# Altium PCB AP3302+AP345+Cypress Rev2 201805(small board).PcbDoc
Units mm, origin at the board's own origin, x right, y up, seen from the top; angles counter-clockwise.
Board outline 316.8 x 235.8 mm, 2 copper layers (Top Layer, Bottom Layer); 44 components, 66 nets, 160 pads, 51 vias.
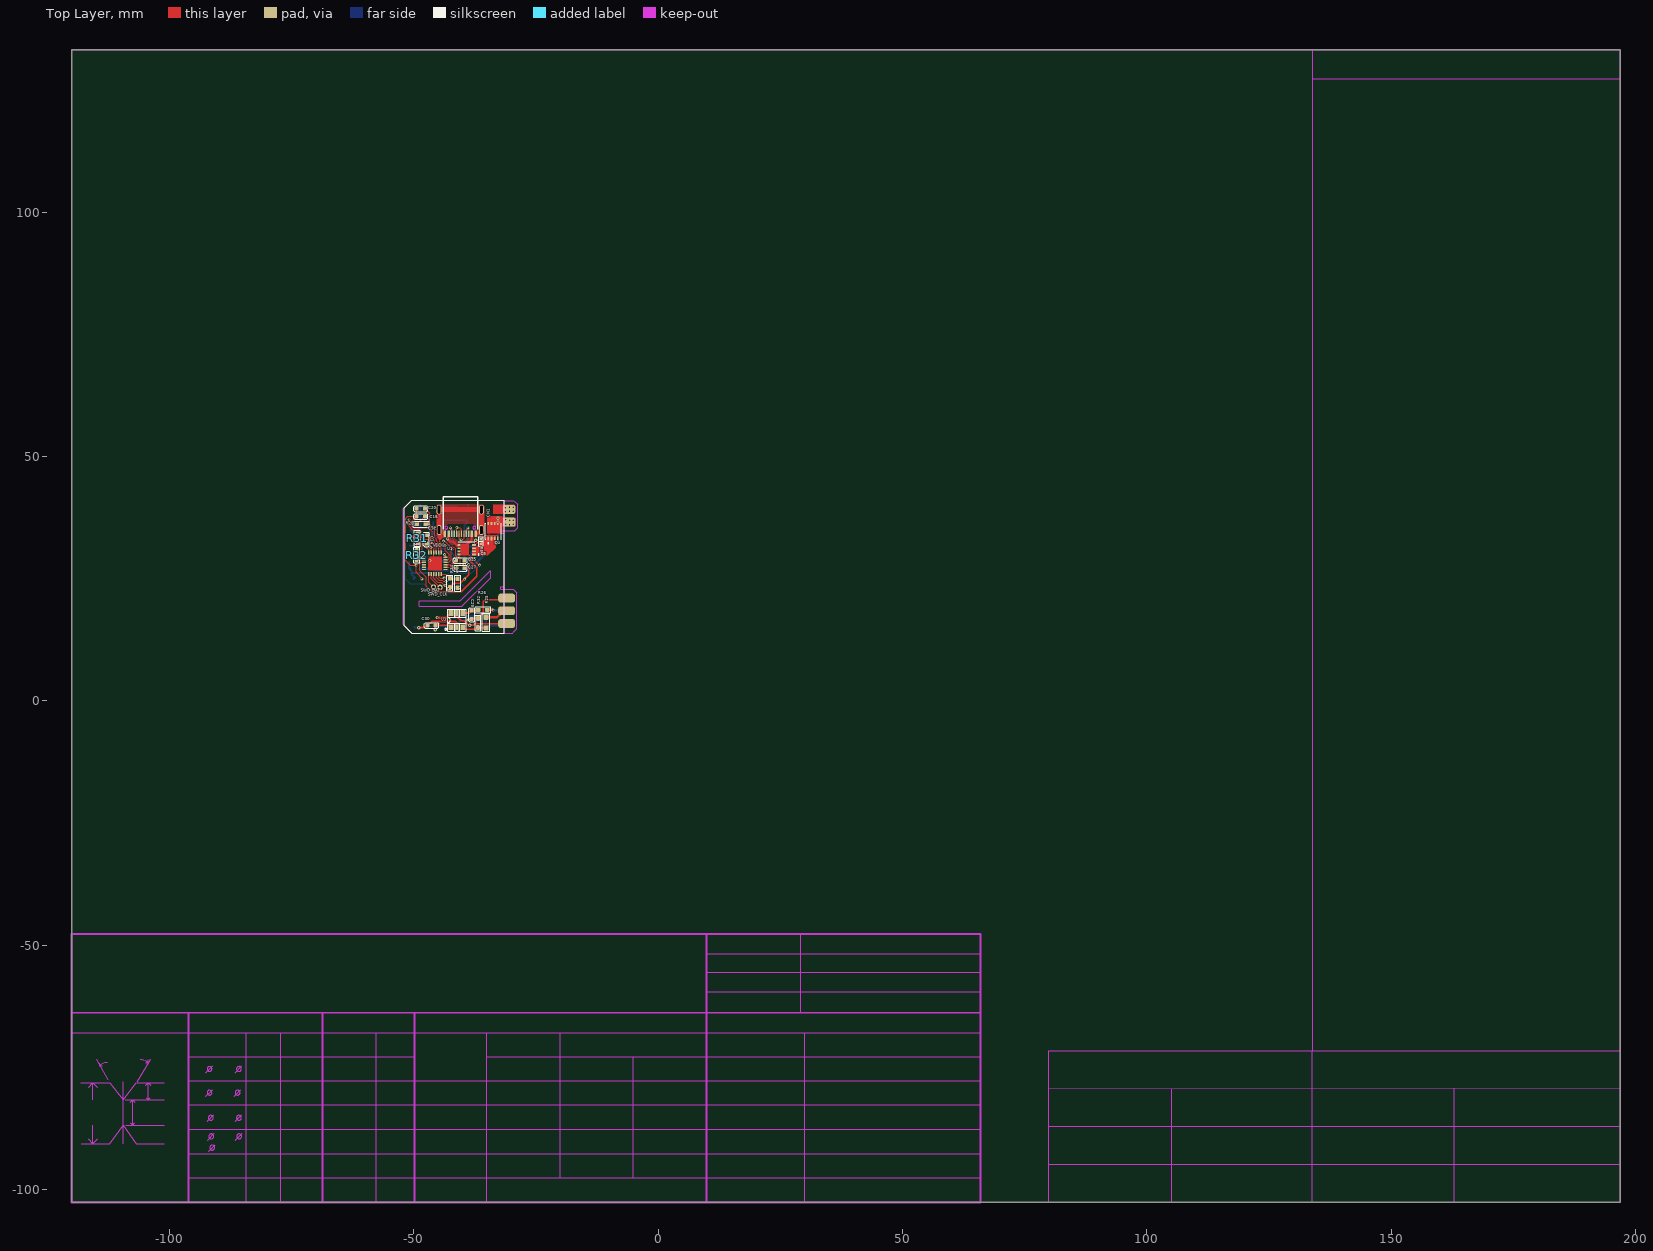
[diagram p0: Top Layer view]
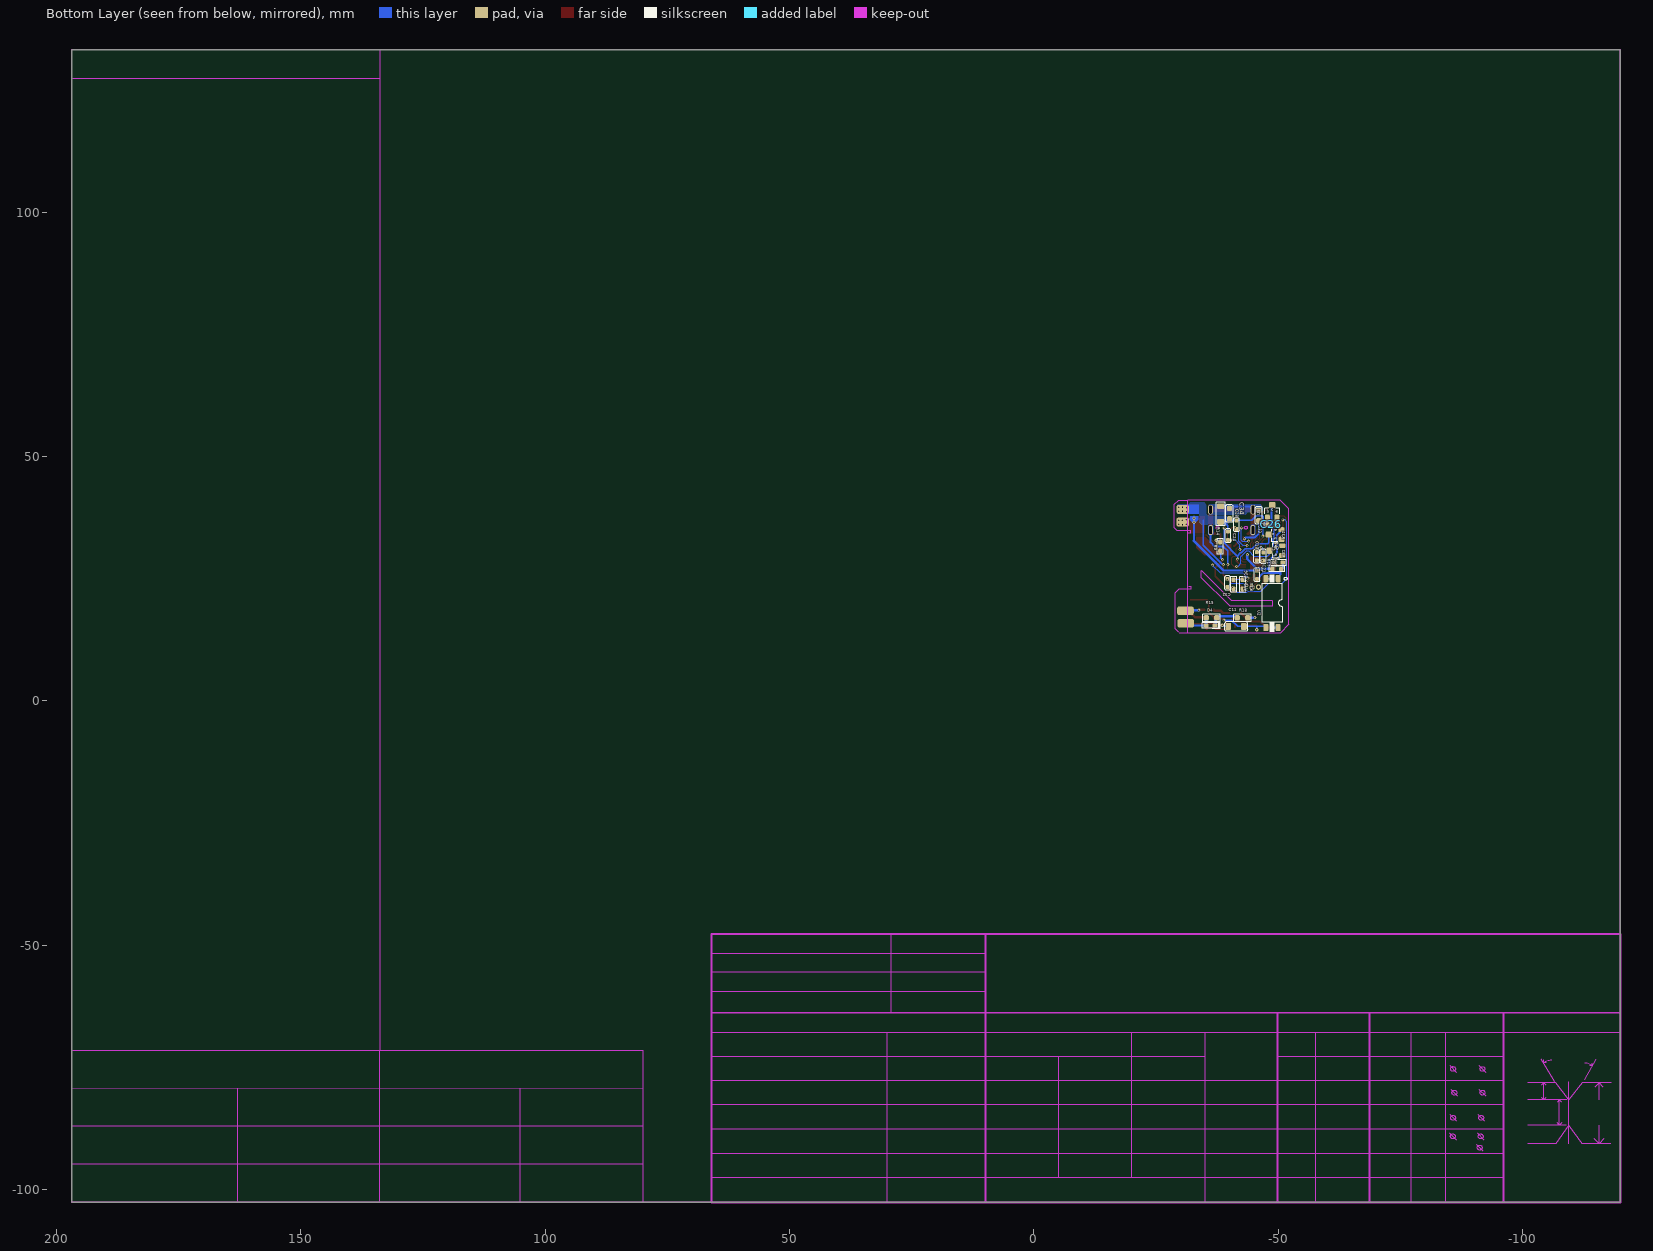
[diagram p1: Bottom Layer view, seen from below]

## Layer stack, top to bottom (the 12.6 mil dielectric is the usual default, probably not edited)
Top Layer: signal copper 0.0356
Dielectric: core 0.32, FR-4, Dk 4.8
Bottom Layer: signal copper 0.0356

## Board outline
-119.957,-102.573 -119.957,133.227 196.843,133.227 196.843,-102.573

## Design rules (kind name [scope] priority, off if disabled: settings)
Clearance [All] p1: gap=0.2
ComponentClearance [All] p1: gap=0 collisioncheckmode=3 verticalgap=0
HoleSize [All] p1: absolutevalues=TRUE maxlimit=12.7 minlimit=0.025 maxpercent=80.000 minpercent=20.000
PlaneConnect [All] p1: planeconnectstyle=Direct reliefexpansion=0.508 reliefentries=4 reliefconductorwidth=0.254 reliefairgap=0.254
PolygonConnect [All] p1: connectstyle=Direct reliefconductorwidth=0.254 reliefentries=4 polygonreliefangle="90 Angle"
RoomDefinition ATTP4I3B [InComponentClass('ATTP4I3B')] p1: confinementstyle=ConfineIn formatcopy=TRUE lockcomponents=FALSE outline 197.992,-103.673 202.591,-103.673 202.591,-95.523 197.992,-95.523
RoutingVias [All] p1: holewidth=0.711 width=1.27 viastyle="Through Hole" minholewidth=0.203 minwidth=0.254 maxholewidth=0.711 maxwidth=1.27
SolderMaskExpansion [All] p1: expansion=0.102
TestPointUsage [All] p1: valid=0 allowmultiple=FALSE
Testpoint [(IsPad And (OnTopLayer Or OnBottomLayer))] p1: side=3 testpointundercomponent=TRUE minsize=1.016 maxsize=2.54 preferedsize=1.524 minholesize=0 maxholesize=1.016 preferedholesize=0.813 testpointgrid=0.025 style=297 order=0-112345678
Width [All] p1: maxlimit=3 minlimit=0.2 preferedwidth=0.3
16 further rules are at their usual default settings.

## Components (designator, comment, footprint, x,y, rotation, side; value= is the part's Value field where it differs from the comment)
C11 "4.7uF/50V" 1206C(W) -41.35,15.25 r0 bottom
C14 "1uF/50V" 0603C(W) -47.4,33.05 r270 top
C16 "22nF/50v" 0603C(W) -48.55,37.75 r180 top (schematic designator C19)
C18 "1uF/50V" 0603C(W) -45.6,29.6 r270 bottom
C20 "150nF/50V" 0603C(W) -48.55,39.35 r180 top (schematic designator C31)
C21 "100nF/50V" 0603c(w) -46.95,29.55 r270 bottom
C24 "390pF/50V" 0603C(W) -39.7,33.8 r90 bottom
C25 "390pF/50V" 0603C(W) -40.5,28.75 r0 top
C26 "2.2UF/50V" 0603C(W) -48.6,36.2 r180 bottom
C27 "390pF/50V" 0603C(W) -40.45,27.15 r0 top
C28 "390pF/50V" 0603C(W) -41.45,36.05 r90 bottom
C29 "220pF/50V" 0603C(W) -38.15,17.65 r90 top
C30 "1nF/50V" 0603C(W) -46.35,15.45 r180 top
C32 "100nF/50V" 0603c(w) -39.6,24.15 r270 bottom (schematic designator C21)
C33 "1uF/50V" 0805C(W) -46,38 r90 bottom
C34 "1nF/200v" 0805c(W) -40,38.3 r270 bottom (schematic designator C17)
C36 "100nF/50V" 0603c(w) -45.65,25.8 r90 bottom (schematic designator C21)
CN1 "TYPE C RECEPTACLE" "USB type C" -36.15,34.95 r90 top locked
D4 "1N4148WS" SMD-(SOD-523) -36.15,15.45 r0 bottom
Q4 "DMP2007UFG" INF-PG-TSDSON-8-1_V -33.75,34.75 r270 top
Q5 "DMP2007UFG" INF-PG-TSDSON-8-1_V -39.15,30.95 r0 top
Q6 "MOS-N2" sot-23-1 -49.25,34.05 r90 bottom (schematic designator Q3)
Q7 "MOS-N2" sot-23-1 -49.4,30.75 r90 bottom (schematic designator Q3)
R5 "100K" 0402(W) -36.25,32.65 r90 top
R9 "51R" 0603(W) -38.1,31.6 r90 bottom
R11 "1K" 0603(W) -49.7,27 r180 bottom
R14 "5 mR" 1206(W) -38.2,38.25 r270 bottom
R15 "51R" 0805(W) -36.25,17.05 r0 bottom
R17 "4.7K" 0603(W) -50,28.3 r0 bottom
R18 "10R" 0805(W) -42.75,16.95 r180 bottom
R20 "5.25K" 0603(W) -48.45,36.15 r0 top
R25 "390K" 0805(W) -35.25,15.95 r270 top
R26 "1k" 0603(W) -35.85,18.65 r180 top
R31 "100K" 0603(W) -49.25,33.3 r270 top (schematic designator R33)
R32 "1K" 0603(W) -36.85,15.95 r270 top
R32 "100K" 0603(W) -49.4,29.85 r270 top (schematic designator R33)
R33 "100K" 0603(W) -42.7,23.85 r270 bottom
R34 "100K" 0603(W) -42.6,24.15 r270 top
RT2 "100K" 0603(w) -41,24.1 r90 top (schematic designator NTC2)
RT3 "100K" 0603(w) -40.85,23.85 r90 bottom (schematic designator NTC1)
U1 "CYPD3175" TQFN24_4X4 -45.65,28.15 r180 top
U2 "PC-4PIN" "SO-4(P10) - photocoupler" -48.7,20 r270 bottom
U3 "AP3302" SOT-23-6 -41.15,16.55 r90 top
U5 "MOS-N2" sot-23-1 -48.75,38.9 r180 bottom (schematic designator Q3)

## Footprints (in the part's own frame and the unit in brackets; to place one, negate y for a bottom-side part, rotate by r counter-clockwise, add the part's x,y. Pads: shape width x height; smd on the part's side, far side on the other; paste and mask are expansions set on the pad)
0402(W) [mm]
  rrect50% 0.5x0.5 smd mask+0.03: 1(-0.475,0) 2(0.475,0)
  silkscreen extent -0.95,-0.45 0.95,0.45, body extent -0.5,-0.25 0.5,0.25, height 0.35
0603(W) [mm]
  rrect50% 0.95x0.8 smd mask+0.03: 1(-0.925,0) 2(0.925,0)
  silkscreen extent -1.6,-0.6 1.6,0.6, body extent -0.77,-0.42 0.78,0.43, height 0.45
0603(w) [mm]
  rrect50% 0.95x0.8 smd mask+0.03: 1(-0.925,0) 2(0.925,0)
  silkscreen extent -1.6,-0.6 1.6,0.6, body extent -0.77,-0.42 0.78,0.43, height 0.45
0603C(W) [mm]
  rrect50% 0.8x0.8 smd mask+0.03: 1(-0.85,0) 2(0.85,0)
  silkscreen extent -1.45,-0.6 1.45,0.6, body extent -0.8,-0.45 0.8,0.4, height 0.8
0603c(w) [mm]
  rrect50% 0.8x0.8 smd mask+0.03: 1(-0.85,0) 2(0.85,0)
  silkscreen extent -1.45,-0.6 1.45,0.6, body extent -0.8,-0.45 0.8,0.4, height 0.8
0805(W) [mm]
  rrect50% 1.05x1.1 smd mask+0.03: 1(-1.15,0.05) 2(1,0.05)
  silkscreen extent -1.88,-0.7 1.72,0.8, body extent -1.07,-0.57 0.93,0.68, height 0.45
0805C(W) [mm]
  rrect50% 1.05x1.1 smd mask+0.03: 1(-1.125,0) 2(1.025,0)
  silkscreen extent -1.85,-0.75 1.75,0.75, body extent -1.05,-0.62 0.95,0.63, height 0.6
0805c(W) [mm]
  rrect50% 1.05x1.1 smd mask+0.03: 1(-1.125,0) 2(1.025,0)
  silkscreen extent -1.85,-0.75 1.75,0.75, body extent -1.05,-0.62 0.95,0.63, height 0.6
1206(W) [mm]
  rrect50% 1.2x1.5 smd mask+0.03: 1(-1.6,0) 2(1.6,0)
  silkscreen extent -2.4,-0.95 2.4,0.95, body extent -1.6,-0.8 1.6,0.8, height 0.55
1206C(W) [mm]
  rrect50% 1.2x1.5 smd mask+0.03: 1(-1.6,0) 2(1.6,0)
  silkscreen extent -2.4,-0.95 2.35,0.95, body extent -1.6,-0.8 1.6,0.8, height 0.79
INF-PG-TSDSON-8-1_V [mm] "TSDSON, 8-Leads, Body 3.3x3.3mm, Pitch 0.65mm"
  rect 0.8x0.34 smd: 1(1.5,-0.975) 2(1.5,-0.325) 3(1.5,0.325) 4(1.5,0.975)
  rect 0.65x0.34 smd: 5(-1.575,0.975) 6(-1.575,0.325) 7(-1.575,-0.325) 8(-1.575,-0.975)
  Top Layer region: -1.25,-1.145 0.46,-1.145 0.46,1.145 -1.25,1.145
  silkscreen extent -1.65,-1.65 2.57,1.65, body extent -1.65,-1.65 1.65,1.65, height 1.1
SMD-(SOD-523) [mm]
  rrect50% 1.05x0.8 smd: 1(0.95,0) 2(-0.925,0)
  silkscreen extent -2,-0.7 1.7,0.7
"SO-4(P10) - photocoupler" [mm]
  rrect50% 1.5x1 smd: 1(-5.025,1.25) 2(-5.025,-1.25) 3(4.975,-1.25) 4(4.975,1.25)
  silkscreen extent -5.9,-2.1 5.9,3.12
sot-23-1 [mm]
  rrect50% 1x1.3 smd: 1(-1,-1.4) 3(1,-1.4)
  rrect50% 1.3x1.3 smd: 3(0,1.2)
  silkscreen extent -1.5,-0.6 1.53,0.58
SOT-23-6 [mm]
  rect 1.2x1 smd: 1(-1.45,1.2) 3(-1.45,-1.2) 4(1.45,-1.2) 6(1.45,1.2)
  rect 1.2x0.5 smd: 2(-1.45,0) 5(1.45,0)
  silkscreen extent -2.3,-1.9 2.25,2.48
TQFN24_4X4 [mm]
  rect 0.8x0.3 smd: 1(2.2,-1.25) 2(2.2,-0.75) 3(2.2,-0.25) 4(2.2,0.25) 5(2.2,0.75) 6(2.2,1.25) 13(-2.2,1.25) 14(-2.2,0.75) 15(-2.2,0.25) 16(-2.2,-0.25) 17(-2.2,-0.75) 18(-2.2,-1.25)
  rect 0.3x0.8 smd: 7(1.25,2.2) 8(0.75,2.2) 9(0.25,2.2) 10(-0.25,2.2) 11(-0.75,2.2) 12(-1.25,2.2) 19(-1.25,-2.2) 20(-0.75,-2.2) 21(-0.25,-2.2) 22(0.25,-2.2) 23(0.75,-2.2) 24(1.25,-2.2)
  Top Layer region: -1.4,1.4 1.4,1.4 1.4,-0.975 0.975,-1.4 -1.4,-1.4
  silkscreen extent 2.9,-1.78 3.38,-0.82
"USB type C" [mm]
  oval 2.1x0.9 hole 0.5 slot 1.6 at 0 deg: 0(0.016,-0.007) 1(0.016,8.643)
  oval 2x1 hole 0.5 slot 1.6 at 0 deg: 0(4.196,8.643) 0(4.196,-0.007)
  rrect50% 1.34x0.25 smd: A1(-0.764,1.018) A4(-0.764,1.818) A9(-0.764,6.818) A12(-0.764,7.618) B1(-0.764,7.368) B4(-0.764,6.568) B9(-0.764,2.068) B12(-0.764,1.268)
  rrect50% 1.34x0.27 smd: A5(-0.764,3.068) A6(-0.764,4.068) A7(-0.764,4.568) A8(-0.764,5.568) B5(-0.764,6.068) B6(-0.764,5.068) B7(-0.764,3.568) B8(-0.764,2.568)
  Keep-Out Layer circle w0.1: c0.506,7.208 r0.3
  Keep-Out Layer circle w0.1: c0.506,1.428 r0.3
  silkscreen extent 0.16,0.77 6.82,7.82

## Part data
C11 C29 C30: library part Cap, "Capacitor"
C14 C16 C18 C20 C21 C24 C25 C26 C27 C28 C32 C33 C34 C36: library part CAP, "Capacitor"
CN1: library part "USB TYPE-C"
D4: library part D, "Diode"
Q4 Q5: library part "BSZ086P03NS3 G", "P-Channel OptiMOS P3 Power-Transistor, -30燰 VDS, -40燗 ID, -55 to 150 degC, PG-TSDSON-8-1, Reel, Green"
Q6 Q7 U5: "MOS"
R5 R9 R14 R20 R31 R32 R33 R34 RT2 RT3: library part RES2
R11 R15 R17 R18 R25 R26 R32: library part Res3, "Resistor"
U2: "Optical coupling"
U3: library part IC_SG6848T

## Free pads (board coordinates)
  round 1.1 hole 0.6: 0(-45.95,23.3) 0(-44.6,23.25)
  rrect50% 3.4x1.8 smd: 0(-31,15.85) 1(-31,18.45) 2(-31,21.05)
  rrect50% 2.6x1.8 smd: 2(-30.45,36.6) 2(-30.45,39.2)
  rrect50% 2.6x1.8 smd far side: 3(-30.45,36.6) 3(-30.45,39.2)
  rrect50% 3.4x1.8 smd far side: 4(-31,18.45) 5(-31.05,15.9)

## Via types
v1: diameter 0.61, hole 0.305, Top Layer to Bottom Layer, tented both sides, 27 vias
v2: diameter 0.7, hole 0.3, Top Layer to Bottom Layer, 14 vias
v3: diameter 0.7, hole 0.3, Top Layer to Bottom Layer, tented both sides, 4 vias
v4: diameter 0.6, hole 0.3, Top Layer to Bottom Layer, 3 vias
v5: diameter 0.6, hole 0.3, Top Layer to Bottom Layer, tented both sides, 3 vias

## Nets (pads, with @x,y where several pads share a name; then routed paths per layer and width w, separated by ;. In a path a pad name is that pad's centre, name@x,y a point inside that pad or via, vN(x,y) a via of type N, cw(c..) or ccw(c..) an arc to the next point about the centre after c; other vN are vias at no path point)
9: C32.2 U1.9 | length 8
  Top Layer w0.2: U1.9@-45.9,25.8 -45.9,25.1 -45.1,24.3 -44.366,24.3 -43.666,23.6 v1(-43.55,23.6)
  Bottom Layer w0.2: v1(-43.55,23.6) -43.25,23.6 -42.9,23.95 -40.25,23.95 C32.2
10: R33.1 RT3.2 U1.10 | length 5.7
  Top Layer w0.2: U1.10 -45.4,25.35 -44.8,24.75 -44.25,24.75 -44,24.5 -43.5,24.5 v1(-43.4,24.4)
  Bottom Layer w0.2: v1(-43.4,24.4) -43.025,24.775 R33.1 ; R33.1 RT3.2
12: R34.1 RT2.2 U1.12 | length 3.8
  Top Layer w0.2: U1.12 -43.475,25.95 R34.1 -42.55,25.025 RT2.2
CC1: C25.1 CN1.A5 Q6.3@-48.05,34.05 U1.15 | length 20.4
  Top Layer w0.25: CN1.A5 -39.218,35.032 v5@-38.9,35.35
  Top Layer w0.3: U1.15@-43.35,27.9 -42.2,27.9 -41.375,28.725 C25.1
  Bottom Layer w0.3: Q6.3@-48.05,34.05 -48.05,32.35 -47.85,32.15 -45.65,32.15 -44.75,31.25 -44.6,31.1 -43.25,31.1 -42.45,30.3 -42.229,30.3 -41.65,29.721 ; v1(-41.65,29) -41.65,29.721 ; v5(-38.9,35.4) -38.9,32.35 -41.529,29.721 -41.65,29.721
CC2: C27.1 CN1.B5 Q7.3@-48.2,30.75 U1.14 | length 26
  Top Layer w0.2: v1(-43.9,32.7) -43.6,32.7 -42.5,31.6 -41.9,31.6 -41.4,31.1 -41.4,30.876 ; U1.14@-43.3,27.4 C27.1@-41.15,27.4 ; v5(-42.5,35.4) -42.5,35.382 -42.218,35.1 CN1.B5 ; -41.4,30.85 -41.4,29.7 -41.2,29.5 -40.7,29.5 -40.5,29.3 -40.5,27.95 C27.1
  Bottom Layer w0.2: Q7.3@-48.3,30.75 -48.3,30.2 -47.65,29.55 -45.1,29.55 -44.05,30.6 -43.4,30.6 -42.35,29.55 -42.35,28.15 -41.7,27.5 v1@-41.55,27.5 ; v1(-43.9,32.7) -43.727,32.527 -42.773,32.527 -42.4,32.9 v5@-42.4,35.405
  Bottom Layer w0.3: v5(-42.5,35.4) v5@-42.4,35.405
  other v1: -41.45,27.55
D+: C28.1 CN1.A6 CN1.B6 U1.17 | length 12.9
  Top Layer w0.2: v1@-43.554,31.78 -43.554,30.85 -42.75,30.046 -42.75,29.15 -42.75,29.1 -42.95,28.9 U1.17
  Top Layer w0.25: CN1.B6 -41.218,35.232 -41.1,35.35 v1(-41.15,35.45) -40.5,35.45 -40.218,35.168 CN1.A6 CN1.A6@-40.218,33.582
  Bottom Layer w0.2: v1(-43.6,31.8) -42.866,31.8 -41.95,32.716 -41.95,34.55 -41.25,35.25 -41.15,35.35 v1(-41.15,35.45)
D-: C24.1 CN1.A7 CN1.B7 U1.16 | length 10.5
  Top Layer w0.2: U1.16 -42.8,28.4 -42.3,28.9 -42.3,30.8 v1(-42.15,30.95) ; CN1.A7 -40.718,33.168 -40.5,32.95 v1(-40.3,32.95) -40.05,32.95 -39.7,33.3 -39.7,34.168 CN1.B7
  Bottom Layer w0.2: v1(-42.15,30.95) -42.15,31.95 -41.15,32.95 v1(-40.3,32.95) C24.1
D_Q6: 
D_Q7: 
EARTH: C25.2 C27.2 C33.2 C34.1 CN1.0 CN1.1 CN1.A1 CN1.A12 CN1.B1 CN1.B12 R14.1 U1.19 | length 39.4
  Top Layer w0.2: -44.65,33.45 -44.65,32.55 -44.4,32.3 -44.4,31.65 U1.19 ; C25.2 -39.65,27.2 C27.2
  Top Layer w0.5: CN1.1@-44.548,34.966 CN1.A12 ; CN1.A1 -36.923,34.186 -36.143,34.966 CN1.0@-36.143,35.793
  Top Layer w1: CN1.1 -44.793,39.146 -36.143,39.146 CN1.0@-36.143,34.966 ; -44.65,33.45 -44.65,33.85
  Bottom Layer w0.3: -38.95,39.85 -38.95,40.25
  Bottom Layer w0.4: v1(-39.656,27.894) -39.656,30.694 -38.75,31.6 -37,31.6 -36.15,32.45 CN1.0@-36.15,35.1
  Bottom Layer w0.5: CN1.0@-44.793,39.146 -44.149,39.79 -41.22,39.79
G_Q6: Q6.1 R31.1 U1.1 | length 7.9
  Top Layer w0.2: R31.1 R31.1@-49.15,34.225 ; R31.1@-48.975,34.225 R31.1@-49.15,34.225 ; U1.1 -48.2,29.75 -48.2,32.55 -49.15,33.5 R31.1@-49.15,34.225
  Top Layer w0.5: v1(-50.7,33.6) -49.875,33.6 R31.1
  Bottom Layer w0.5: Q6.1@-50.7,33 -50.7,33.05 v1(-50.7,33.6)
G_Q7: Q7.1 R32.2@-49.4,28.925 U1.2 | length 3.4
  Top Layer w0.2: R32.2@-49.375,28.9 U1.2
  Top Layer w0.5: v1(-49.9,29.15) -49.625,29.15 -49.4,28.925 R32.2@-49.375,28.9
  Bottom Layer w0.5: Q7.1@-50.9,29.75 Q7.1 -50.5,29.75 v1(-49.9,29.15)
GND: C11.1 C29.1 C30.1 pad.2@-31,21.05 R32.1@-36.85,16.875 U2.3 U3.1 | length 24
  Top Layer w0.3: v3(-45.6,14.6) -45.6,15.35 C30.1 -42.7,15.45 U3.1 ; v4(-38.85,16.55) -38.6,16.8 C29.1 -38.075,16.875 -36.85,16.875 R32.1@-36.65,16.875 ; R32.1@-36.95,16.975 -35.79,18.135 -35.79,20.31 -35.4,20.7 pad.2@-31.95,20.7
  Bottom Layer w0.3: U2.3@-47.3,15.175 -47.225,15.25 -45.55,15.25 ; v3(-45.6,14.6) -45.6,15.2 -45.55,15.25 ; v4(-38.85,16.55) -40.35,16.55 -41.65,15.25 C11.1 -45.55,15.25
NetBD1_1: 
NetBD1_2: 
NetBD1_3: 
NetC2_1: 
NetC4_1: pad.4 R26.1 | length 2.8
  Top Layer w0.5: R26.1@-34.9,18.65 v4@-33.8,18.65
  Bottom Layer w0.5: v4(-33.75,18.6) pad.4@-32.05,18.6
NetC4_2: D4.1 pad.5 R15.2 | length 5
  Bottom Layer w0.5: R15.2@-35.45,17.2 -35.475,17.175 -35.32,16.951 -35.25,16.85 -35.25,15.5 D4.1 pad.5@-32.05,15.45
NetC5_1: 
NetC6_2: 
NetC13_1: 
NetC14_2: C14.2 U1.24 | length 2.1
  Top Layer w0.2: C14.2 -47.4,31.4 -46.9,30.9 U1.24
NetC17_1: 
NetC17_2: 
NetC19_1: C16.1 R20.1 | length 2.3
  Top Layer w0.2: R20.1 -47.775,37.75 C16.1
NetC19_2: C16.2 C20.2 R17.2 U1.21 U2.2 | length 31.8
  Top Layer w0.2: -51.6,28.75 -51.6,28.65 -50.75,27.8 v1(-49.5,27.8) -49.5,26.35 -48.2,25.05 v1(-48.3,25) ; -51.6,28.8 -51.6,37.35 -51.2,37.75 C16.2 ; C20.2 C16.2 ; U1.21 -45.4,32.05 -45.7,32.35 -45.7,32.8 -46.15,33.25 -46.15,34.6 -47,35.45 -50,35.45 -50.45,35.9 -50.45,36.7 C16.2
  Bottom Layer w0.2: v1@-49.65,27.725 v1@-49.538,27.837 ; v1(-49.5,27.8) -49.075,28.225 R17.2 ; v1(-48.3,25) U2.2@-47.475,25
NetC22_2: 
NetC23_2: 
NetC26_2: 
NetC29_2: C29.2 R26.2 U3.4 | length 3.4
  Top Layer w0.5: U3.4 -38.65,18 C29.2 -36.925,18.5 R26.2
NetC30_2: C30.2 U2.4 U3.2 | length 10.3
  Top Layer w0.4: v3(-48.95,15) -47.65,15 C30.2 -47.1,15.45 -46.3,16.25 -41.4,16.25 -41.15,16 U3.2
  Bottom Layer w0.4: U2.4@-49.8,15.175 -49.8,15.05 -49.75,15 v3(-48.95,15)
NetC31_1: C20.1 R20.2 U1.20 | length 11.2
  Top Layer w0.2: C20.1 -46.75,38.4 -46.75,36.925 R20.2 -46.8,36.15 -45.7,35.05 -45.7,33.384 -45.3,32.984 -45.3,32.634 -44.9,32.234 U1.20
NetD1_1: 
NetD2_1: 
NetD3_1: 
NetD4_2: D4.2 R15.1 R18.1 | length 6.3
  Bottom Layer w0.5: R18.1 -41.3,17.3 -37.7,17.3 R15.1 ; R15.1@-37.4,17.2 -37.3,17.1 -37.2,17 -37.2,15.575 D4.2
NetD5_1: 
NetD6_1: R9.1 U1.3 | length 24.4
  Top Layer w0.2: U1.3 -48.45,28.4 -48.75,28.1 -48.75,26.6 -47.45,25.3 -47.45,23.5 -46.25,22.3 -46.2,22.3
  Top Layer w0.3: -46.2,22.3 -40.25,22.3 -37.05,25.5 -37.05,27.25 -38.6,28.8 v1(-38.6,28.9)
  Bottom Layer w0.3: v1(-38.6,28.9) -38.2,29.3 -38.2,30.575 R9.1
NetD6_2: 
NetF1_1: 
NetF1_2: 
NetLF1_4: 
NetNTC1_2: 
NetNTC2_2: 
NetQ2_1: 
NetQ3_1: 
NetQ4_1: Q4.1 Q4.2 Q4.3 Q5.1 Q5.2 Q5.3 R5.1
NetQ4_4: Q4.4 Q5.4 R5.2 R9.2 | length 8.4
  Top Layer w0.2: v3(-37.3,32.9) -37.5,32.7 -37.5,32.075 Q5.4 -37.375,31.925 -36.213,33.087 -35.35,33.95 -32.95,33.95 -32.775,33.775 Q4.4
  Bottom Layer w0.3: R9.2 -37.725,32.9 v3(-37.3,32.9)
NetR8_2: 
NetR11_2: C36.1 R11.2 R17.1 U2.1 | length 9.9
  Bottom Layer w0.3: U2.1@-49.95,24.85 U2.1@-49.95,25.15
  Bottom Layer w0.4: R17.1@-50.95,28.4 -50.95,27.35 -50.625,27.025 R11.2@-50.625,26.85 ; R11.2@-50.925,27.1 -50.475,26.65 -50.475,25.95 U2.1@-49.7,25.175 ; -50.475,26.2 -46.9,26.2 C36.1 ; U2.1@-50,25.05 U2.1@-50,25.175
NetR12_1: pad.1 R25.1 | length 4.4
  Top Layer w0.5: R25.1 -33,17.1 pad.1@-32.065,18.035 ; pad.1@-31.9,18.45 pad.1
NetR13_2: 
NetR17_2: 
NetR18_2: R18.2 U3.6 | length 4.8
  Top Layer w0.5: v4(-45.2,17.05) -43.3,17.05 U3.6
  Bottom Layer w0.5: v4(-45.2,17.05) -43.75,17.05 R18.2@-43.65,17.05
NetR25_2: R25.2 R32.2@-36.85,15.025 U3.3 | length 5.4
  Top Layer w0.3: U3.3 -39.55,14.7 -37.175,14.7 -36.85,15.025 -35.275,15.025 R25.2
  Top Layer w0.5: R25.2@-35.4,14.75 R25.2
NetR36_2: 
S_Q6: C26.2 Q6.3@-50.65,35.05 Q7.3@-50.8,31.75 R31.2 R32.1@-49.4,30.775 U5.3@-49.75,37.5 | length 9.5
  Top Layer w0.2: R32.1@-49.4,30.775 -49.4,32.225 R31.2
  Bottom Layer w0.3: Q7.3@-50.9,31.75 -50.8,31.75 -50,31.75 -49.65,32.1 v1(-49.65,32.25) -49.65,33.9 -50.65,34.9 -50.65,35.05 -49.5,36.2 C26.2 -49.75,36.5 U5.3@-49.75,37.5
S_Q7: 
SGND: C14.1 C18.2 C21.2 C24.2 C26.1 C28.2 C32.1 C34.2 R14.2 R33.2 R34.2 U1.22 U5.1 | length 41.9
  Top Layer w0.2: v1(-46.841,33.73) -46.841,33.376 -46.1,32.634 -46.1,32.184 -45.8,31.884 -45.8,31.135 -45.9,31.035 -45.9,29.1
  Top Layer w0.3: C14.1 -47.35,33.9 v1(-46.841,33.73) ; R34.2@-42.7,23.2 -41.8,24.1 -40.5,24.1 -38.75,25.85 v1(-38.75,27.9)
  Bottom Layer w0.2: -47.35,28.7 C18.2@-45.85,28.7
  Bottom Layer w0.3: U5.1 C26.1 -47.7,36.2 -46.8,35.3 v1(-46.841,33.73) ; C26.1@-47.6,36.2 -46.9,36.9 -46.9,37.7 -46.7,37.9 -45.5,37.9 -44.55,36.95 -39.25,36.95 -38.95,36.65 -39.7,35.9 C24.2 ; v1@-38.577,27.927 -34.65,31.853 -34.65,37.05
  other v1: -42.95,23 -39.55,24.95 -46.7,28.7
SWD_CLK: pad.0@-44.6,23.25 U1.8 | length 3.5
  Top Layer w0.2: U1.8 -46.4,25 -44.65,23.25 pad.0@-44.6,23.25
SWD_DAT: pad.0@-45.95,23.3 U1.7 | length 3
  Top Layer w0.2: U1.7 -46.9,24.25 pad.0@-45.95,23.3
VBUS_IN: C36.2 Q4.5 Q4.6 Q4.7 Q4.8 R11.1 U1.18 U5.3@-48.75,40.1 | length 45.9
  Top Layer w0.2: Q4.8 Q4.5 v2@-32.775,37.65
  Top Layer w0.3: U1.18 -43.45,29.65
  Top Layer w0.4: v1(-43.65,29.95) -43.65,29.85 -43.45,29.65
  Bottom Layer w0.4: U5.3@-48.75,40.1 -48.65,40 -48.65,35.55 -49.1,35.1 -49.1,33.25 -48.9,33.05 -48.9,32 -49.75,31.15 -49.75,30.35 -48.15,28.75 -48.15,27.05 ; R11.1@-48.725,27.05 R11.1@-48.675,27 ; v2@-32.75,37.4 v2@-32.75,37.65
  Bottom Layer w0.5: R11.1@-48.725,27.05 -45.732,27.05 C36.2@-45.698,27.016 ; C36.2@-45.8,26.9 -43.65,29.05 v1(-43.65,29.95) ; C36.2@-45.75,26.7 -38.8,26.7 -32.677,32.823 ; -32.75,32.9 -32.75,33.4 v2@-32.75,37.65
  other v2: -32.75,36.6 -32.75,37.35
VCC: C11.2 pad.0@-31,15.85 U3.5 | length 13.1
  Top Layer w0.3: U3.5 -41.15,17.25 -40.3,16.4 -39.655,16.4 -38.755,15.5 v3(-38.55,15.5) -37.85,15.5 -37.5,15.85 pad.0@-32.15,15.85
  Top Layer w0.6: pad.0@-32.15,15.85 pad.0@-31,15.85
  Bottom Layer w0.3: C11.2 -38.8,15.25 v3(-38.55,15.5)
VDDO: C18.1 C21.1 RT2.1 RT3.1 U1.23 | length 38.2
  Top Layer w0.2: v1@-51.05,36.9 -51.05,35.8 -50.3,35.05 -48.85,35.05 -48.4,34.6 -48.4,33.55 -47.9,33.05 -47.1,33.05 -46.7,32.65 -46.7,32.5 -46.5,32.3 v1(-46.5,31.4) ; U1.23 v1@-46.4,31.4 ; v1@-46.4,31.45 v1@-46.4,31.4 ; v1@-46.375,31.425 v1@-46.4,31.4
  Bottom Layer w0.2: v1(-50.95,37.05) -51.4,37.05 -51.75,36.7 -51.75,25 -50.8,24.05 -50.8,24 -50.775,23.975 -47.925,23.975 -46.35,22.4 -43.75,22.4 -43.477,22.127 -41.723,22.127 v1(-40.6,23.25) ; C21.1 -46.95,31.15 -46.65,31.45 v1@-46.5,31.5 ; v1@-46.5,31.6 -46.2,31.6 -45.85,31.25 C18.1@-45.85,30.45
VOUT: C33.1 CN1.A4 CN1.A9 CN1.B4 CN1.B9 Q5.5 Q5.6 Q5.7 Q5.8 U1.11 | length 26.4
  Top Layer w0.2: U1.11 -44.9,25.45 -44.6,25.15 v1(-43.75,25.15) ; Q5.8 Q5.7 ; -39.65,30.2 -39.1,30.2 ; -38.9,30.1 -36.75,27.95 v1(-36.5,27.8)
  Top Layer w0.4: v5(-43.05,33.15) -42.5,32.6 -41.85,32.6 -40.95,31.7 ; v5@-43.05,33.29 -42.82,33.52 ; -39.35,31.75 -38.15,32.95 CN1.B9@-38.15,34.186
  Bottom Layer w0.2: v1(-43.75,25.15) -43.75,25.2 -42.859,26.091 -38.209,26.091 v1(-36.5,27.8)
  Bottom Layer w0.4: C33.1@-46,36.625 -46,34.25 -45.2,33.45 -43.35,33.45 v5(-43.05,33.15)
pads on no net: CN1.A8 CN1.B8 U1.4 U1.5 U1.6 U1.13
copper on no net:
  other v2: -30.4,36.1 -31.15,36.15 -29.6,36.15 -30.35,37 -29.6,37 -31.15,37.05 -31.25,38.75 -30.4,38.8 -29.6,38.8 -31.25,39.55 -30.4,39.6 -29.6,39.6

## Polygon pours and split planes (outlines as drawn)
VOUT on Top Layer "Bottom-No Net" (solid, remove dead copper, pour order 44): -43.35,33.35 -43.35,32.95 -42.9,32.5 -42.35,31.95 -41.8,31.95 -41.75,31.95 -41.35,31.55 -41.3,31.5 -40.25,31.5 -40.25,32.5 -40.75,32.5 -41.25,33 -41.6,33.35 -43.35,33.35
EARTH on Top Layer "MidLayer2-No Net" (solid, remove dead copper, pour order 52): -44.5,35.35 -44.5,35.15 -44.25,34.9 -43.55,34.9 -43.4,34.75 -43.4,33.55 -43.55,33.4 -45,33.4 -45.3,33.7 -45.3,35.1 -45.05,35.35
VOUT on Top Layer "MidLayer2-No Net" (solid, remove dead copper, pour order 62): -38.3,34.45 -38,34.45 -37.85,34.3 -37.85,32.9 -38.85,31.9 -40.3,31.9 -40.3,32.05 -39.1,33.25 -38.45,33.25 -38.3,33.4
EARTH on Top Layer "MidLayer2-No Net" (solid, remove dead copper, pour order 47): -37.45,34.8 -36.95,34.8 -36.4,35.35 -35.75,35.35 -35.65,35.25 -35.65,33.85 -35.8,33.7 -36.75,33.7 -37,33.45 -37.4,33.45 -37.5,33.55 -37.5,34.75
NetQ4_1 on Top Layer "Top Layer-No Net" (solid, pour order 48): -38.05,29.8 -37.3,29.8 -34.35,32.75 -33.25,32.75 -33.25,33.65 -35,33.65 -37.2,31.45 -38.05,31.45
EARTH on Top Layer "Top Layer-No Net" (solid, pour order 54): -43.4,33.55 -45.15,33.55 -45.3,33.7 -45.3,40 -45.1,40.2 -35.85,40.2 -35.5,39.85 -35.5,34.233 -36.033,33.7 -36.75,33.7 -37,33.45 -37.4,33.45 -37.5,33.55 -37.5,35.95 -37.8,36.25 -43,36.25 -43.4,35.85
SGND on Bottom Layer "Top Layer-No Net" (solid, pour order 65): -35.3,38.35 -35.75,37.9 -39.35,37.9 -39.75,37.5 -39.75,36.25 -39.55,36.05 -34.3,36.05 -33.8,36.55 -33.8,38.3 -33.25,38.85 -32.35,38.85 -31.75,39.45 -31.75,40.4 -32,40.65 -34.8,40.65 -35.3,40.15
EARTH on Bottom Layer "MidLayer2-No Net" (solid, remove dead copper, pour order 78): -46.407,40.2 -35.892,40.2 -35.65,39.9 -35.65,38.45 -35.892,38.15 -43.305,38.15 -43.708,38.65 -46.649,38.65 -46.85,38.9 -46.85,39.65

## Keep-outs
Keep-Out Layer:
  circle w0.15: c-91.204,-91.37 r0.5
  circle w0.15: c-91.757,-75.273 r0.5
  circle w0.15: c-85.754,-75.27 r0.5
  circle w0.15: c-91.754,-80.12 r0.5
  circle w0.15: c-86.004,-80.12 r0.5
  circle w0.15: c-91.504,-85.27 r0.5
  circle w0.15: c-85.754,-85.27 r0.5
  circle w0.15: c-91.404,-89.07 r0.5
  circle w0.15: c-85.704,-89.07 r0.5
  lines w0.2: -119.957,-67.873 9.943,-67.873 ; -118.057,-90.581 -112.207,-90.591 ; -118.057,-78.073 -112.207,-78.073 -109.369,-81.573 -106.707,-78.073 ; -116.607,-89.573 -115.607,-90.573 ; -116.507,-78.973 -115.607,-78.073 ; -115.607,-86.823 -115.607,-90.573 ; -115.607,-81.573 -115.607,-78.073 ; -114.958,-73.323 -112.569,-77.443 ; -114.707,-78.973 -115.607,-78.073 ; -114.607,-89.573 -115.607,-90.573 ; -114.207,-74.123 -114.207,-74.623 ; -113.707,-74.623 -114.207,-74.623 ; -112.671,-73.986 ccw(c-112.671,-76.159) -114.207,-74.623 ; -112.207,-90.573 -109.369,-86.823 -106.707,-90.573 -101.057,-90.573 ; -109.369,-90.573 -109.369,-77.943 ; -108.957,-81.593 -101.057,-81.593 ; -108.869,-86.793 -101.057,-86.793 ; -108.019,-86.293 -107.519,-86.793 ; -108.019,-82.093 -107.519,-81.593 ; -107.519,-86.573 -107.519,-81.593 ; -107.019,-86.293 -107.519,-86.793 ; -107.019,-82.093 -107.519,-81.593 ; -106.686,-78.073 -101.057,-78.073 ; -106.519,-77.843 -103.785,-73.256 ; -105.914,-73.416 cw(c-105.914,-75.83) -104.313,-74.023 ; -104.807,-78.573 -104.307,-78.073 -103.807,-78.573 ; -104.807,-74.023 -104.307,-74.023 ; -104.719,-81.193 -104.319,-81.593 -103.919,-81.193 ; -104.319,-81.573 -104.319,-78.143 ; -104.307,-73.973 -104.307,-73.373 ; -96.057,-97.573 65.843,-97.573 ; -96.057,-92.673 -68.757,-92.673 ; -96.007,-87.623 -68.757,-87.623 ; -96.007,-82.573 -68.657,-82.573 9.843,-82.573 ; -96.007,-77.673 -68.757,-77.673 9.943,-77.673 65.943,-77.673 ; -96.007,-72.823 -49.857,-72.823 ; -92.507,-76.023 -91.132,-74.648 ; -92.504,-80.87 -91.129,-79.495 ; -92.254,-86.02 -90.879,-84.645 ; -92.154,-89.82 -90.779,-88.445 ; -91.954,-92.12 -90.579,-90.745 ; -86.754,-80.87 -85.379,-79.495 ; -86.504,-86.02 -85.129,-84.645 ; -86.504,-76.02 -85.129,-74.645 ; -86.454,-89.82 -85.079,-88.445 ; -84.257,-102.473 -84.257,-67.873 ; -77.157,-102.573 -77.157,-67.873 ; -68.657,-92.573 -49.757,-92.573 ; -68.557,-87.573 9.843,-87.573 ; -67.457,-67.873 -49.757,-67.873 ; -57.657,-102.573 -57.657,-67.973 ; -49.857,-92.573 9.943,-92.573 65.843,-92.573 ; -35.057,-102.573 -35.057,-67.873 ; -35.057,-72.773 9.943,-72.773 29.143,-72.773 65.943,-72.773 ; -31.7,23.4 -32.2,23.4 -32.2,22.85 -29.65,22.85 -28.9,22.1 -28.9,14.8 -29.65,14.05 ; -31.55,34.3 -32.1,34.3 -32.1,34.85 -29.3,34.85 -28.75,35.4 -28.75,40.25 -29.4,40.9 ; -31.5,41 -29.5,41 ; -29.75,13.9 -31.5,13.9 ; -20.057,-97.573 -20.057,-67.873 ; -5.057,-97.573 -5.057,-72.773 ; 9.943,-87.573 65.943,-87.573 ; 9.943,-82.573 65.943,-82.573 ; 9.943,-67.873 65.943,-67.873 ; 9.943,-59.473 65.943,-59.473 ; 9.943,-55.473 65.943,-55.473 ; 9.943,-51.673 65.943,-51.673 ; 29.143,-63.773 29.143,-47.673 ; 30.043,-102.573 30.043,-67.873 ; 79.943,-102.573 79.943,-71.525 196.839,-71.533 ; 79.943,-94.773 196.839,-94.775 ; 79.943,-86.973 196.839,-87.025 ; 79.943,-79.273 196.839,-79.275 ; 105.089,-102.573 105.089,-79.275 ; 133.837,-102.667 133.837,-71.525 ; 133.843,133.236 133.855,-71.528 ; 133.843,127.327 196.843,127.327 ; 162.839,-102.595 162.839,-79.175 ; -107.519,-86.793 -107.519,-86.793 ; -107.519,-81.593 -107.519,-81.593 ; -31.5,13.9 -31.5,41.05 -50.4,41.05 -52.15,39.3 -52.15,15.65 -50.4,13.9 -31.5,13.9 ; -119.957,-102.573 196.843,-102.573 196.843,133.227 -119.957,133.227 -119.957,-102.573
  lines w0.203: -40.1,19.4 -48.85,19.4 -48.85,20.4 -48.75,20.5 -40.45,20.5 -34.3,26.65 ; -40.033,19.467 -34.25,25.25 -34.25,26.6
  lines w0.4: -119.957,-63.773 9.943,-63.773 65.943,-63.773 ; -96.057,-102.573 -96.057,-63.773 ; -68.657,-102.473 -68.657,-63.773 ; -49.857,-102.573 -49.857,-63.773 ; 9.943,-102.573 9.943,-47.673 ; -119.957,-102.573 -119.957,-47.673 65.943,-47.673 65.943,-102.573 -119.957,-102.573
  text "Revisions Note" at 147.949,128.427 h3
  text "REV-T02:" at 134.569,124.594 h2
  text "1.Q2、D2、C10、C11、ZD1、R16等元器件由锡膏工艺改为红胶工艺；" at 135.418,122.24 h2
  text "2.U51周边电路变更，且改为红胶工艺；" at 135.418,120.462 h2
  text "3.次级电路优化；" at 135.418,118.684 h2
  text "2015.3.25" at 180.148,114.644 h2
  text "REV-T03:" at 135.349,110.424 h2
  text "1， 删除原先测试用的的431线路" at 137.13,107.81 h1.52
  text "2， 高压启动D2，D3取电位置从bridge上换到X 电容；" at 137.13,106.032 h1.52
  text "3， Bridge由4个SMB 二极管改成一个SMD的2A的bridge" at 137.13,104.254 h1.52
  text "4， 增加LED  cable线" at 137.13,102.476 h1.52
  text "5. C51,C58输出两颗电容由D8 330uF改为D6.3 220uF" at 137.13,100.698 h1.52
  text "6.输入输出端变更；" at 137.13,98.92 h1.52
  text "2015.4.23" at 179.549,95.224 h2
  text "REV-T04:" at 136.369,91.004 h2
  text "1.增加胶垫丝印位置；" at 139.099,87.592 h2
  text "2.C2封装改为EC-6.5X11-P2.5-C；" at 139.099,85.814 h2
  text "3.保险丝丝印改为：T2A(L)/250V" at 139.05,83.19 h2
  text "4.D2\D3线路变更；" at 139.07,80.72 h2
  text "2015.5.25" at 176.72,76.79 h2
  text "REV-T05:" at 136.21,72.46 h2
  text "1.增加电容C12.&R18;" at 140.659,69.552 h2
  text "2.调整ICT测试点 U51 pin5 pin8,,ZD1,增加pin4;" at 140.72,66.59 h2
  text "3.BD1变更封装BD-MBSL；" at 140.789,63.202 h2
  text "4.C57改为R59贴片0603（W）;" at 140.749,60.702 h2
  text "5.ID/OP+间距加大增加白油条；" at 140.799,57.472 h2
  text "2015.6.11" at 170.149,54.292 h2
  text "REV-T06:" at 136.55,53.31 h2
  text "1.增加电容C12.C14C15C16删除R18" at 140.999,50.402 h2
  text "2.增大LF1 ,BD1焊盘；" at 141.06,47.44 h2
  text "3.拼板变更；" at 141.129,44.052 h2
  text "4.增加ICT测试点移动位置压棒下脚点；" at 141.129,40.782 h2
  text "2015.7.23" at 172.079,37.592 h2
  text "REV-T07:" at 136.75,35.47 h2
  text "1.R16由0603改1206" at 141.199,32.562 h2
  text "2.R58、LF1放电针间距调整为0.4mm" at 141.26,29.6 h2
  text "2015.8.6" at 172.188,27.432 h2
  text "注意：" at -119.257,-46.573 h2.5
  text "10" at -33.457,-48.973 h0.8
  text "104-03020002M0" at 30.659,-50.25 h2.5
  text "1.  Top overlay/Bottom overlay层丝印油墨要求：使用高阻抗绝缘油墨，绝缘阻抗≥1x10  欧." at -118.957,-50.473 h2.5
  text "PCB料号" at 11.143,-50.673 h2.5
  text "2. 厂商须在Top Overlay 层标注生产周期, 防火等级，GP字样." at -118.857,-53.173 h2.5
  text "材质/板厚/铜厚" at 11.043,-54.573 h2.5
  text "FR-4/1.0mm / 2OZ" at 31.178,-54.59 h2.5
  text "FR-1,FR-4,CEM-1,M-228F板材必须符合UL认证,并标识UL的认证标识,型号,编号." at -116.057,-55.773 h2.5
  text "FR-1,FR-4,CEM-1,M-228F,22F板材必须符合CQC认证,并标识CQC的认证标识,型号,编号." at -116.157,-58.273 h2.5
  text "TOP/Bottom丝印" at 11.143,-58.273 h2.5
  text "Top:White  Bottom:White" at 30.078,-58.29 h2.5
  text "3.via通孔塞油处理，表面盖油处理。" at -118.757,-61.273 h2.5
  text "HAL (无铅喷锡,锡厚2~20um)" at 31.178,-62.29 h2.5
  text "PCB表面处理" at 11.243,-62.373 h2.5
  text "PCB V-CUT要求" at -116.657,-66.773 h2.5
  text "PCB孔径公差" at -87.257,-66.773 h2.5
  text "PCB导线铜厚要求" at -26.457,-66.773 h2.5
  text "PCB厚度公差" at -65.557,-66.873 h2.5
  text "其它要求" at 31.343,-66.873 h2.5
  text "PCB hole" at -95.157,-69.873 h2.5
  text "PCB厚度" at -67.557,-70.373 h2.5
  text "公差" at -55.957,-70.373 h2.5
  text "NPTH" at -83.657,-71.173 h2.5
  text "PTH" at -75.257,-71.173 h2.5
  text "成品----单面板" at -34.457,-71.173 h2.5
  text "成品----双面板及多层板" at -16.857,-71.173 h2.5
  text "PCB模冲公差" at 12.143,-71.173 h2.5
  text "士0.1" at 44.643,-71.673 h2.5
  text "(mm)" at -93.257,-72.173 h2.5
  text "(mm)" at -65.957,-72.273 h2.5
  text "(mm)" at -56.557,-72.273 h2.5
  text "o" at -109.557,-72.773 h0.5
  text "o" at -106.257,-72.873 h0.5
  text "铜厚规格" at -46.457,-73.273 h2.5
  text "25-45" at -112.057,-74.373 h2.5
  text "V-CUT处 PCB单板" at 11.743,-74.773 h2.2
  text "+0.1" at -82.757,-75.073 h2.5
  text "外层导线厚度" at -19.157,-75.173 h2.5
  text "0.5 -0.7" at -95.257,-76.023 h1.5
  text "内层导线厚度" at -3.957,-76.173 h2.5
  text "士0.1" at -56.457,-76.273 h2.5
  text "导线铜箔厚度" at -34.157,-76.273 h2.5
  text "0.8～1.0" at -67.457,-76.373 h2.5
  text "士0.2" at 44.643,-76.373 h2.5
  text "士0.075" at -76.857,-76.473 h2.5
  text "Shenzhen Huntkey Electronics Co., Ltd." at 80.443,-76.573 h2
  text "TITLE:" at 134.02,-76.88 h2.5
  text "HKA03020015-6A--REV-T07-SCH-T07" at 142.7,-76.88 h3.5
  text "分板后公差(包括毛边)" at 10.743,-76.973 h2.2
  text "-0" at -82.157,-77.173 h2.5
  text "(铜箔加镀铜)" at -17.457,-77.173 h2
  text "+0.1" at -82.957,-79.973 h2.5
  text "0.3mm" at -103.557,-80.573 h2.5
  text "0.8 -1.0" at -95.257,-80.873 h1.5
  text "1.2" at -65.257,-81.073 h2.5
  text "士0.12" at -56.957,-81.073 h2.5
  text "1/2OZ (17um)" at -49.157,-81.073 h2.5
  text "≥12um" at -30.657,-81.173 h2.5
  text "≥33um" at -15.657,-81.173 h2.5
  text "≥12um" at -0.657,-81.173 h2.5
  text "孔位/孔距偏移公差" at 10.943,-81.273 h2.5
  text "士0.075" at -76.857,-81.473 h2.5
  text "士0.1" at 44.643,-81.473 h2.5
  text "-0" at -82.457,-82.173 h2.5
  text "0.4mm" at -106.807,-83.923 h2.5
  text "DTAE: 2015.8.6" at 80.679,-84.59 h2
  text "若线宽＜0.5mm,则公差不得超出线宽的20%;" at 30.543,-84.673 h2
  text "SHEET   OF" at 165.839,-84.775 h2.5
  text "SCALE :A3" at 110.443,-84.873 h2.5
  text "REV:T07" at 141.143,-84.973 h2.5
  text "1.0mm" at -118.057,-85.073 h2.5
  text "≥25um" at -0.757,-85.873 h2.5
  text "1.1 -3.4" at -94.357,-85.973 h1.5
  text "导线线宽公差" at 12.843,-85.973 h2.5
  text "士0.1" at -83.257,-86.073 h2.5
  text "士0.075" at -76.857,-86.073 h2.5
  text "+/-0.1mm" at -106.857,-86.173 h2.5
  text "1.6" at -64.957,-86.173 h2.5
  text "士0.14" at -56.857,-86.173 h2.5
  text "1OZ (35um)" at -48.357,-86.173 h2.5
  text "≥26um" at -30.757,-86.173 h2.5
  text "≥46um" at -15.757,-86.173 h2.5
  text "若线宽 ≥ 0.5mm,则公差士0.1mm" at 30.643,-86.873 h2
  text "4.0 ," at -95.257,-89.673 h1.5
  text "若线距＜0.5mm,则公差不得超出线距的20%;" at 30.643,-89.673 h2
  text "6.0" at -89.557,-89.773 h1.5
  text "+0.1" at -82.957,-89.873 h2.5
  text "+0.1" at -75.057,-89.873 h2.5
  text "≥56um" at -0.857,-90.673 h2.5
  text "士0.14" at -56.957,-90.773 h2.5
  text "≥57um" at -30.757,-90.773 h2.5
  text "1.6以上" at -67.157,-90.873 h2.5
  text "2OZ (70um)" at -48.457,-90.873 h2.5
  text "≥76um" at -15.757,-90.873 h2.5
  text "导线间距公差" at 12.743,-90.973 h2.5
  text "-0" at -82.357,-91.873 h2.5
  text "-0" at -74.457,-91.873 h2.5
  text "若线距 ≥ 0.5mm,则公差士0.1mm" at 30.643,-91.873 h2
  text "3.5" at -95.157,-92.073 h1.5
  text "APPRDVED" at 138.743,-92.373 h2.5
  text "C" at -109.957,-92.573 h1.5
  text "CHECKED" at 111.443,-92.573 h2.5
  text "PREPARED" at 82.143,-92.673 h2.5
  text "FILE NO" at 172.643,-92.773 h2.5
  text "L" at -109.707,-94.323 h1.5
  text "≥107um" at -15.957,-95.573 h2.5
  text "≥91um" at -0.957,-95.573 h2.5
  text "≥91um" at -30.857,-95.673 h2.5
  text "3OZ (105um)" at -48.957,-95.773 h2.5
  text "PAD宽度公差" at 12.843,-95.973 h2.5
  text "不得超出单边PAD宽度的20%" at 30.643,-95.973 h2.5
  text "贯孔(VIA)孔壁" at -49.257,-99.573 h2.5
  text "绿油厚度范围" at 12.843,-100.973 h2.5
  text "10um~25um" at 31.043,-100.973 h2.5
  text "最小值≥ 20um,孔壁光滑均匀" at -34.057,-101.073 h2.5
  text "内的铜厚要求" at -48.757,-102.073 h2.5

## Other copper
Top Layer:
  rectangle net VBUS_IN: -33.6,35.65 -29.2,37.5
  rectangle: -33.8,38.3 -29.4,40.15
  rectangle net VBUS_IN: -34.95,34.3 -31.85,37.85
  region net NetQ4_1: -33.25,33.644 -35.006,33.644 -37.2,31.45 -38.05,31.45 -38.05,29.8 -34.8,29.8 -33.25,31.35
Bottom Layer:
  rectangle net SGND: -33.8,38.3 -29.4,40.15
  region net VBUS_IN: -33.65,37.8 -33.65,37.05 -32.95,36.35 -32.55,36.35 -31.85,37.05 -31.95,37.75 -32.3,37.8
  region net EARTH: -45.3,35.85 -45.3,34.15 -45.05,33.9 -44.55,33.9 -44.35,34.1 -44.35,35.85 -44.6,36.1 -45.05,36.1
  region net EARTH: -36.65,35.85 -36.65,34.15 -36.4,33.9 -35.9,33.9 -35.7,34.1 -35.7,35.85 -35.95,36.1 -36.4,36.1

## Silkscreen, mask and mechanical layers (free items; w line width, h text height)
Top Overlay:
  lines w0.2: -51.9,15.4 -51.9,39.55 -50.4,41.05 -31.5,41.05 -31.5,13.9 -50.4,13.9 -51.9,15.4
  text "VDDO" at -46,31.4 h1
  text "SWD_DAT" at -48.6,22.15 h1
  text "SWD_CLK" at -47.05,21.3 h1
Top Solder:
  rectangle: -35,34.3 -32.5,35.9
  region: -38.75,29.7 -38.75,32.2 -40.35,32.2 -40.35,29.7
Mechanical 2:
  lines w0.1: 10.691,32.524 10.691,44.51
  lines w5: -49.4,20.8 -39.9,20.8 -33.15,27.55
